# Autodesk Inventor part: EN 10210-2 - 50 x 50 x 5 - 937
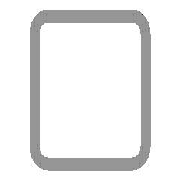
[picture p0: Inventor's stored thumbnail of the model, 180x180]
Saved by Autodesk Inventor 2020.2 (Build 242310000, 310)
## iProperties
_CCFamilyMember: 16
_CCFamilyDisplayName: DIN EN 10210-2 (USAS B17.1 quadratisch) - Rohrleitung — In Klammern angegebene Größen wurden aufgehoben
_FrameMemberDoc: Frame Member File
_Version: 15.0.0
_GetPNFromCC: 1
IsCustomPart: 1
Created: 2019-01
Part Number: EN 10210-2 - 50 x 50 x 5 - 937
Material: Stahl, weich
Description: Rohrleitung
Document SubType Name: Modeling
Standard: DIN
Designer: lutzd
Standard Revision: 2006-07
Standards Organization: DIN
Language: de-DE
Size Designation: 50 x 50 x 5
Categories: <MemberInstance><Categories><Category DisplayName="Profile" InternalName="089c4875-fa83-4c05-b084-43b9cc11f5ed" Mnemonic="GRDR"><CategoryParameter DisplayName="
Stock Number: 50 x 50 x 5
Mass: 6414.42 g
Surface Area: 3191.68 cm^2
Volume: 817.124 cm^3
Density: 7.85 g/cm^3
Appearance: Semi-Polished(8)
G_L: 937,000 mm
G_W: 50,000 mm
G_H: 50,000 mm
DocNumber: ADSK-014265
Folder: .
Dimensions: 50x50x937 mm
Mass: 6,414 kg
+C683FCA0-38E1-4161-81E6-91A887F6B1FB+SCHNITTDETAIL1: Schnittwinkel 90,00 grd
+F6FF46DD-1DA6-4EA5-A205-783A77BDEB22+SCHNITTDETAIL2: Schnittwinkel 90,00 grd
VLT_Material: Stahl, weich
Title: Profil-Bauteil
Author: lutzd
Revision Number: -
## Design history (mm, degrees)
node "Startebene"
node "Endebene"
sketch "Skizze"
  geometry: L1 (-25, -17.5)-(-25, 17.5); L2 (-17.5, 25)-(17.5, 25); L3 (25, 17.5)-(25, -17.5); L4 (17.5, -25)-(-17.5, -25); L5 (-15, 20)-(15, 20); L6 (20, 15)-(20, -15); L7 (15, -20)-(-15, -20); L8 (-20, -15)-(-20, 15); L9 (0, 37.175)-(0, -37.175) reference; L10 (-37.175, 0)-(37.175, 0) reference; A1 r 7.5 centre (-17.5, -17.5) between (-25, -17.5) and (-17.5, -25); A2 r 7.5 centre (-17.5, 17.5) between (-17.5, 25) and (-25, 17.5); A3 r 7.5 centre (17.5, 17.5) between (25, 17.5) and (17.5, 25); A4 r 7.5 centre (17.5, -17.5) between (17.5, -25) and (25, -17.5); A5 r 5 centre (-15, -15) between (-20, -15) and (-15, -20); A6 r 5 centre (-15, 15) between (-15, 20) and (-20, 15); A7 r 5 centre (15, 15) between (20, 15) and (15, 20); A8 r 5 centre (15, -15) between (15, -20) and (20, -15)
  constraints: 16 end point, 16 point on circle, 16 tangent, 8 centre point, 6 equal radius, 4 parallel, 2 perpendicular, 2 other
  dimensions: "d7" = 7.5 radius of A1 (= G_IR); "d10" = 50 distance between parallel lines of L2 L4 (= G_H); "d11" = 50 distance between parallel lines of L1 L3 (= G_W); "d12" = 5 distance between parallel lines of L3 L6 (= G_T); "d15" = 25 distance between parallel lines of L2 L10 (= 0.5 x d10); "d16" = 25 distance between parallel lines of L9 L3 (= 0.5 x d11); "d19" = 5 radius of A5 (= G_T); "d20" = 5 distance between parallel lines of L4 L7 (= G_T)
extrude "Körper" new body sketch "Skizze" stored distance "d3" = 937 (= G_L); taper "d4" = 0 deg
node "Driven Length"
  sketch "Sketch3"
    geometry: L1 (0, 0)-(10, 0) reference
    constraints: 2 end point, 1 horizontal
  workplane "Work Plane3"
  sketch "Sketch4"
    geometry: L1 (-2, 35)-(12, 35) reference; L2 (-2, 972)-(12, 972) reference
    dimensions: "d18" = 937 distance between parallel lines of L1 L2 (derived)
workplane "Arbeitsebene4"
feature "Trennen1"
workplane "Arbeitsebene5"
feature "Trennen2"
sketch "Skizze5"
  geometry: L1 (35, 937)-(0, 937) reference; L2 (17.5, 937)-(17.5, 838); 3 further points
  constraints: 2 end point, 1 coincident, 1 midpoint, 1 point on line, 1 vertical
  dimensions: "d21" = 90 distance of point (17.5, 928) point (17.5, 838); "d22" = 9 distance from line of L1 point (17.5, 928)
hole "Bohrung1" sketch "Skizze5" at (17.5, 928), (17.5, 838) diameter "d23" = 6.647; stored, may be unused: countersink angle "d27" = 90 deg, drill point angle "d29" = 118 deg; dims "d24" = 16, "d25" = 4, "d26" = 2, "d28" = 8
sketch "Skizze6"
  geometry: L1 (937, 0)-(937, -35) reference; L2 (937, -17.5)-(854, -17.5); 3 further points
  constraints: 4 end point, 1 coincident, 1 horizontal, 1 midpoint, 1 point on line, 1 vertical, 2 other
  dimensions: "d30" = 38 distance of point (854, -17.5) point (892, -17.5); "d31" = 45 distance from line of L1 point (892, -17.5)
hole "Bohrung2" sketch "Skizze6" at (854, -17.5), (892, -17.5) diameter "d32" = 6.647; stored, may be unused: countersink angle "d36" = 90 deg, drill point angle "d38" = 118 deg; dims "d33" = 16, "d34" = 4, "d35" = 2, "d37" = 8
body "Solid1"
other parameters: "G_W" = 50 [user parameter; used in 1 equation term], "G_H" = 50 [user parameter; used in 1 equation term], "G_T" = 5 [user parameter; used in 3 equation terms], "G_IR" = 7.5 [user parameter; used in 1 equation term], "G_L" = 937 (= d18) [user parameter; used in 1 equation term], "G_OFFSET_START" = -35 [user parameter; used in 1 equation term], "d13" = 35 (= -G_OFFSET_START), "d14" = 972 (= G_OFFSET_END + B_L), "B_L" = 1022 [user parameter; used in 1 equation term], "d17" = 90 deg
